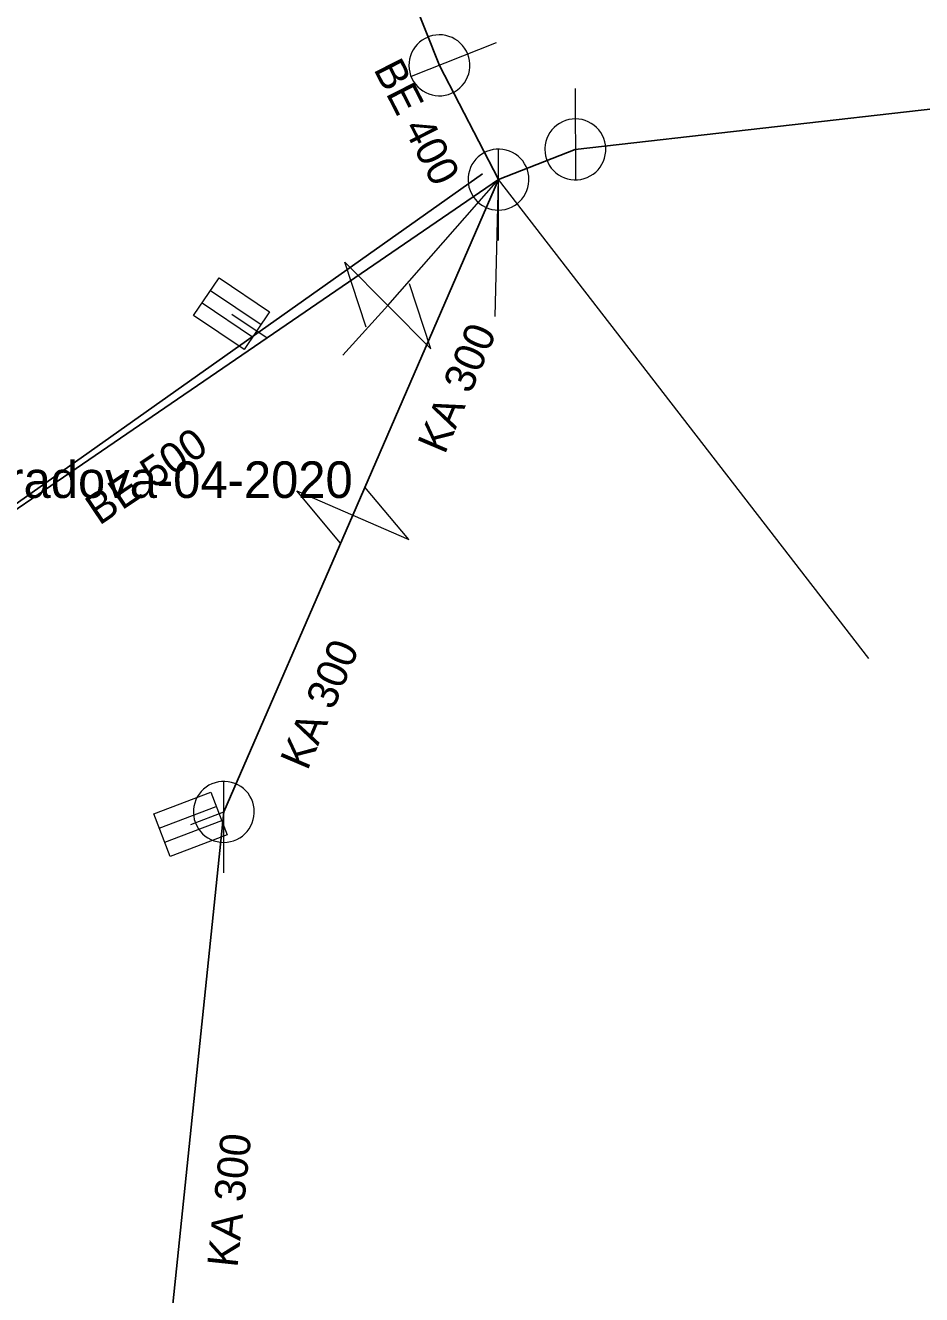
# Model space of a CAD drawing. Extents: x -783064 to -782702, y -1007904 to -1007145.
# Drawn here: x -782825.5 to -782796.1, y -1007838.15 to -1007796.52 of the extents above; entities that cross this region are included whole.
import ezdxf

# ---------------------------------------------------------------- set-up
doc = ezdxf.new("R2010")
doc.units = 0
doc.header["$LTSCALE"] = 0.4
for name, color, linetype, lineweight in [('1', 7, 'Continuous', 13), ('11', 7, 'Continuous', 13), ('14', 7, 'Continuous', 13), ('22', 7, 'Continuous', 13), ('31', 7, 'Continuous', 13)]:
    doc.layers.add(name, color=color, linetype=linetype, lineweight=lineweight)

msp = doc.modelspace()

# ---------------------------------------------------------------- linework, layer by layer
at = {"layer": '11'}
for p, q in [((-782813.609, -1007805.71), (-782809.98, -1007801.58)), ((-782810.094, -1007806.07), (-782809.98, -1007801.58)), ((-782797.829, -1007817.29), (-782809.98, -1007801.58)), ((-782815.087, -1007807.341), (-782813.609, -1007805.71)), ((-782818.73, -1007805.99), (-782817.57, -1007806.77)), ((-782820.07, -1007822.73), (-782818.989, -1007822.32))]:
    msp.add_line(p, q, dxfattribs=at)
at = {"layer": '14', "lineweight": 25}
for p, q in [((-782811.92, -1007797.833), (-782818.609, -1007780.94)), ((-782772.689, -1007796.655), (-782807.46, -1007800.59)), ((-782809.98, -1007801.58), (-782811.92, -1007797.833)), ((-782807.46, -1007800.59), (-782809.98, -1007801.58)), ((-782833.78, -1007817.85), (-782810.509, -1007801.396)), ((-782814.761, -1007812.586), (-782809.98, -1007801.58)), ((-782818.989, -1007822.32), (-782814.761, -1007812.586)), ((-782821.43, -1007845.88), (-782818.989, -1007822.32))]:
    msp.add_line(p, q, dxfattribs=at)
msp.add_lwpolyline([(-782833.46, -1007817.64), (-782817.57, -1007806.77), (-782809.98, -1007801.58)], dxfattribs=at)
at = {"layer": '22'}
for p, q in [((-782810.06, -1007797.096), (-782812.849, -1007798.201)), ((-782807.46, -1007798.589), (-782807.459, -1007801.589)), ((-782809.98, -1007803.58), (-782809.979, -1007800.58)), ((-782819.425, -1007805.213), (-782817.766, -1007806.328)), ((-782819.704, -1007805.627), (-782818.045, -1007806.743)), ((-782818.989, -1007824.32), (-782818.988, -1007821.32)), ((-782821.106, -1007822.849), (-782819.236, -1007822.139)), ((-782820.928, -1007823.316), (-782819.058, -1007822.606))]:
    msp.add_line(p, q, dxfattribs=at)
for points in [[(-782812.287, -1007796.903), (-782812.386, -1007796.948), (-782812.48, -1007797.005), (-782812.568, -1007797.072), (-782812.647, -1007797.146), (-782812.718, -1007797.23), (-782812.779, -1007797.321), (-782812.829, -1007797.418), (-782812.869, -1007797.52), (-782812.898, -1007797.626), (-782812.914, -1007797.734), (-782812.919, -1007797.843), (-782812.911, -1007797.953), (-782812.892, -1007798.061), (-782812.861, -1007798.166), (-782812.819, -1007798.267), (-782812.766, -1007798.363), (-782812.704, -1007798.453), (-782812.631, -1007798.535), (-782812.55, -1007798.608), (-782812.462, -1007798.672), (-782812.366, -1007798.727), (-782812.266, -1007798.77), (-782812.161, -1007798.802), (-782812.054, -1007798.823), (-782811.945, -1007798.832), (-782811.835, -1007798.828), (-782811.726, -1007798.813), (-782811.621, -1007798.787), (-782811.518, -1007798.748), (-782811.42, -1007798.698), (-782811.328, -1007798.64), (-782811.244, -1007798.57), (-782811.167, -1007798.492), (-782811.099, -1007798.406), (-782811.042, -1007798.312), (-782810.995, -1007798.214), (-782810.958, -1007798.11), (-782810.934, -1007798.004), (-782810.921, -1007797.895), (-782810.92, -1007797.785), (-782810.931, -1007797.677), (-782810.954, -1007797.57), (-782810.989, -1007797.465), (-782811.035, -1007797.366), (-782811.091, -1007797.272), (-782811.157, -1007797.185), (-782811.232, -1007797.105), (-782811.316, -1007797.034), (-782811.407, -1007796.974), (-782811.504, -1007796.923), (-782811.606, -1007796.882), (-782811.712, -1007796.854), (-782811.82, -1007796.837), (-782811.929, -1007796.833), (-782812.038, -1007796.839), (-782812.147, -1007796.859), (-782812.252, -1007796.89)], [(-782808.46, -1007800.589), (-782808.453, -1007800.698), (-782808.435, -1007800.806), (-782808.405, -1007800.912), (-782808.365, -1007801.013), (-782808.313, -1007801.11), (-782808.251, -1007801.2), (-782808.179, -1007801.283), (-782808.099, -1007801.357), (-782808.011, -1007801.423), (-782807.917, -1007801.478), (-782807.817, -1007801.523), (-782807.712, -1007801.556), (-782807.605, -1007801.578), (-782807.496, -1007801.588), (-782807.386, -1007801.586), (-782807.278, -1007801.572), (-782807.171, -1007801.547), (-782807.068, -1007801.51), (-782806.97, -1007801.461), (-782806.878, -1007801.403), (-782806.792, -1007801.334), (-782806.715, -1007801.257), (-782806.646, -1007801.171), (-782806.587, -1007801.079), (-782806.539, -1007800.981), (-782806.502, -1007800.878), (-782806.476, -1007800.771), (-782806.462, -1007800.663), (-782806.461, -1007800.553), (-782806.471, -1007800.444), (-782806.492, -1007800.337), (-782806.526, -1007800.233), (-782806.57, -1007800.133), (-782806.625, -1007800.038), (-782806.691, -1007799.95), (-782806.765, -1007799.87), (-782806.848, -1007799.798), (-782806.938, -1007799.736), (-782807.034, -1007799.684), (-782807.136, -1007799.643), (-782807.241, -1007799.613), (-782807.349, -1007799.595), (-782807.459, -1007799.589), (-782807.568, -1007799.595), (-782807.676, -1007799.613), (-782807.781, -1007799.642), (-782807.883, -1007799.683), (-782807.98, -1007799.735), (-782808.07, -1007799.797), (-782808.153, -1007799.868), (-782808.228, -1007799.948), (-782808.293, -1007800.036), (-782808.349, -1007800.13), (-782808.393, -1007800.23), (-782808.427, -1007800.334), (-782808.449, -1007800.442), (-782808.459, -1007800.551)], [(-782808.98, -1007801.58), (-782808.985, -1007801.471), (-782809.003, -1007801.363), (-782809.033, -1007801.257), (-782809.073, -1007801.156), (-782809.125, -1007801.059), (-782809.187, -1007800.969), (-782809.259, -1007800.886), (-782809.339, -1007800.812), (-782809.427, -1007800.746), (-782809.521, -1007800.691), (-782809.621, -1007800.646), (-782809.726, -1007800.613), (-782809.833, -1007800.591), (-782809.942, -1007800.581), (-782810.052, -1007800.583), (-782810.16, -1007800.597), (-782810.267, -1007800.622), (-782810.37, -1007800.659), (-782810.468, -1007800.708), (-782810.56, -1007800.766), (-782810.646, -1007800.835), (-782810.723, -1007800.912), (-782810.792, -1007800.998), (-782810.851, -1007801.09), (-782810.899, -1007801.188), (-782810.936, -1007801.291), (-782810.962, -1007801.398), (-782810.976, -1007801.506), (-782810.979, -1007801.616), (-782810.969, -1007801.725), (-782810.948, -1007801.832), (-782810.914, -1007801.936), (-782810.87, -1007802.036), (-782810.815, -1007802.131), (-782810.749, -1007802.219), (-782810.675, -1007802.299), (-782810.592, -1007802.371), (-782810.502, -1007802.433), (-782810.406, -1007802.485), (-782810.304, -1007802.526), (-782810.199, -1007802.556), (-782810.091, -1007802.574), (-782809.981, -1007802.58), (-782809.872, -1007802.574), (-782809.764, -1007802.556), (-782809.659, -1007802.527), (-782809.557, -1007802.486), (-782809.46, -1007802.434), (-782809.37, -1007802.372), (-782809.287, -1007802.301), (-782809.212, -1007802.221), (-782809.147, -1007802.133), (-782809.091, -1007802.039), (-782809.047, -1007801.939), (-782809.013, -1007801.835), (-782808.991, -1007801.727), (-782808.981, -1007801.618)], [(-782819.146, -1007804.798), (-782817.487, -1007805.914), (-782818.324, -1007807.158), (-782819.983, -1007806.042)], [(-782817.989, -1007822.32), (-782817.994, -1007822.211), (-782818.012, -1007822.103), (-782818.042, -1007821.997), (-782818.082, -1007821.896), (-782818.134, -1007821.799), (-782818.196, -1007821.709), (-782818.268, -1007821.626), (-782818.348, -1007821.552), (-782818.436, -1007821.486), (-782818.53, -1007821.431), (-782818.63, -1007821.386), (-782818.735, -1007821.353), (-782818.842, -1007821.331), (-782818.951, -1007821.321), (-782819.061, -1007821.323), (-782819.169, -1007821.337), (-782819.276, -1007821.362), (-782819.379, -1007821.399), (-782819.477, -1007821.448), (-782819.569, -1007821.506), (-782819.655, -1007821.575), (-782819.732, -1007821.652), (-782819.801, -1007821.738), (-782819.86, -1007821.83), (-782819.908, -1007821.928), (-782819.945, -1007822.031), (-782819.971, -1007822.138), (-782819.985, -1007822.246), (-782819.988, -1007822.356), (-782819.978, -1007822.465), (-782819.957, -1007822.572), (-782819.923, -1007822.676), (-782819.879, -1007822.776), (-782819.824, -1007822.871), (-782819.758, -1007822.959), (-782819.684, -1007823.039), (-782819.601, -1007823.111), (-782819.511, -1007823.173), (-782819.415, -1007823.225), (-782819.313, -1007823.266), (-782819.208, -1007823.296), (-782819.1, -1007823.314), (-782818.99, -1007823.32), (-782818.881, -1007823.314), (-782818.773, -1007823.296), (-782818.668, -1007823.267), (-782818.566, -1007823.226), (-782818.469, -1007823.174), (-782818.379, -1007823.112), (-782818.296, -1007823.041), (-782818.221, -1007822.961), (-782818.156, -1007822.873), (-782818.1, -1007822.779), (-782818.056, -1007822.679), (-782818.022, -1007822.575), (-782818, -1007822.467), (-782817.99, -1007822.358)], [(-782821.283, -1007822.381), (-782819.413, -1007821.671), (-782818.881, -1007823.074), (-782820.751, -1007823.783)]]:
    msp.add_lwpolyline(points, close=True, dxfattribs=at)
at = {"layer": '31'}
for points in [[(-782814.316, -1007806.416), (-782815.02, -1007804.293), (-782812.196, -1007807.126), (-782812.9, -1007805.004)], [(-782815.158, -1007813.503), (-782816.594, -1007811.789), (-782812.926, -1007813.383), (-782814.362, -1007811.669)]]:
    msp.add_lwpolyline(points, dxfattribs=at)

# ---------------------------------------------------------------- texts
at = {"layer": '1'}
for s, rotation, p in [('BE 400', 297, (-782814.092, -1007797.954)), ('KA 300', 67, (-782811.744, -1007810.624)), ('BE 500', 34, (-782823.074, -1007812.941)), ('KA 300', 67, (-782816.249, -1007820.995)), ('KA 300', 84, (-782818.543, -1007837.287))]:
    msp.add_text(s, height=1, rotation=rotation, dxfattribs=at).set_placement(p)
msp.add_text('EX-LN-Louny- Podebradova-04-2020', height=1.2, dxfattribs=at).set_placement((-782841.344, -1007812.023))

doc.saveas('drawing.dxf')
